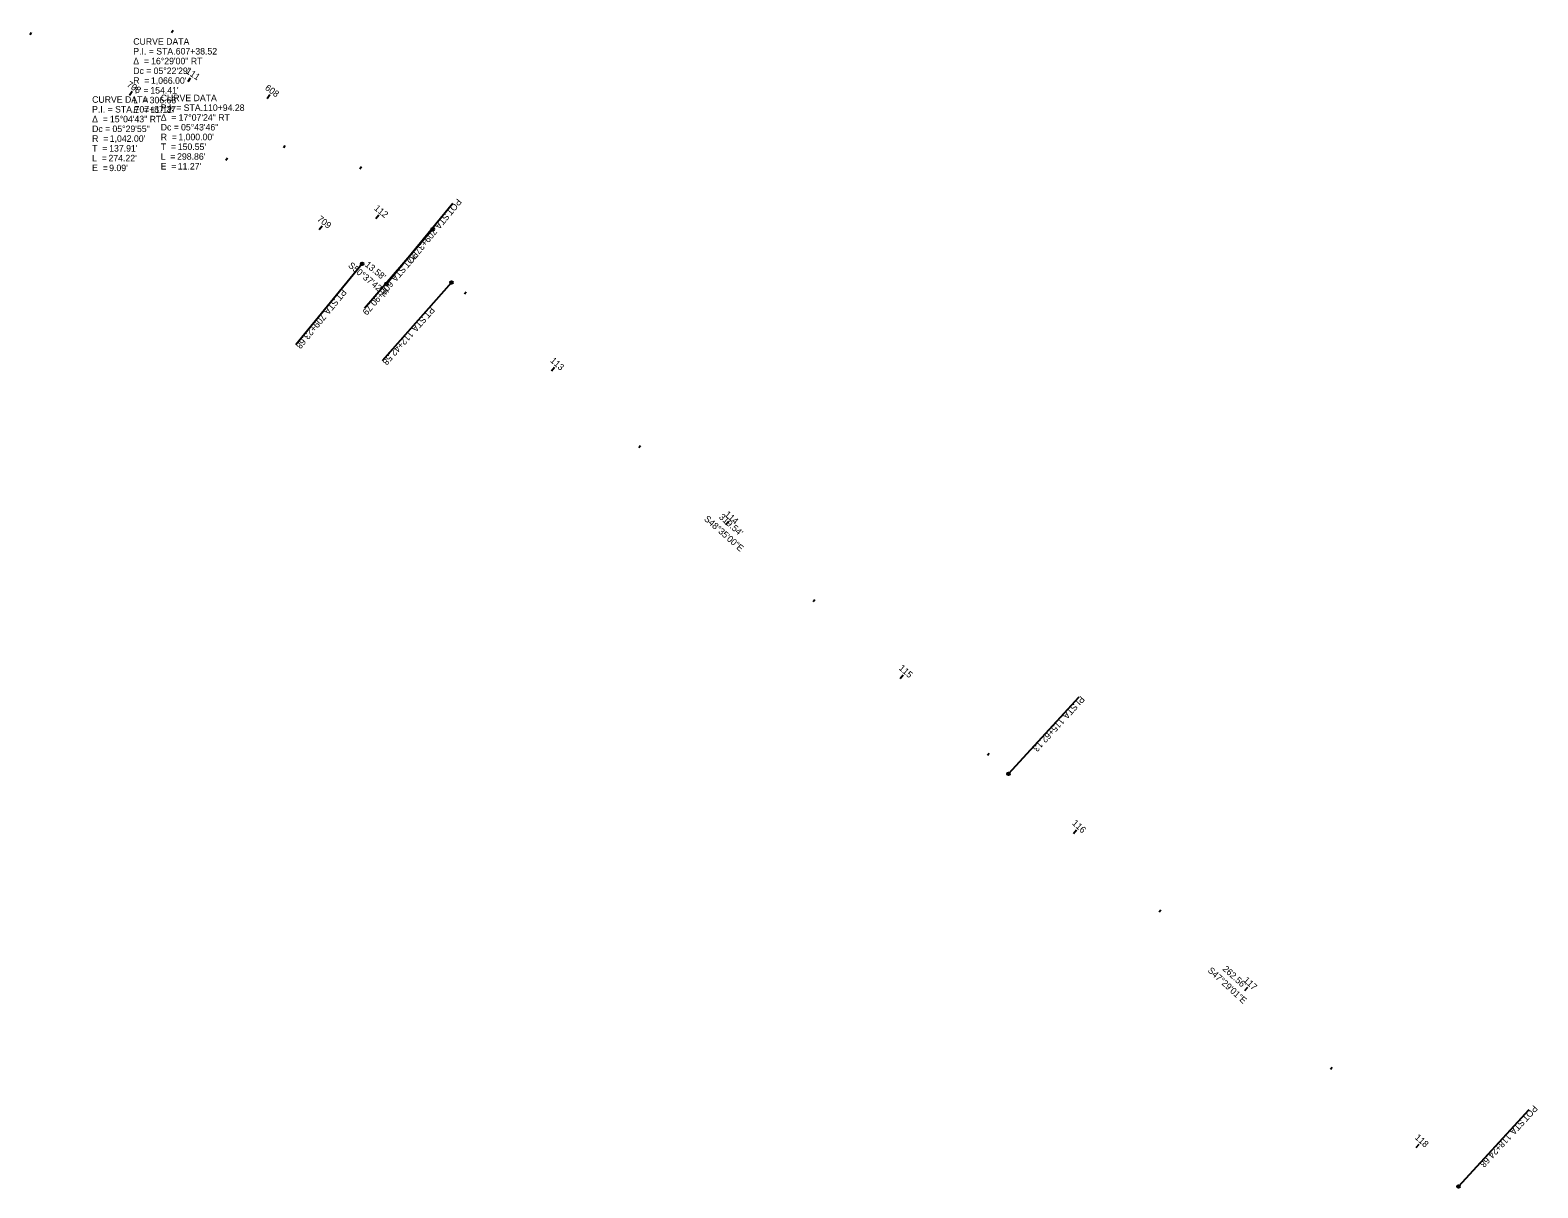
# Model space of a CAD drawing. Extents: x 1600023 to 1602131, y 285824 to 287284.
# Drawn here: x 1601483 to 1602131, y 285824 to 286322 of the extents above; entities that cross this region are included whole.
import ezdxf

# ---------------------------------------------------------------- set-up
doc = ezdxf.new("R2010")
doc.units = 0
for name, color, linetype in [('_CIVIL_CONSTRUCTION', 7, 'Continuous'), ('Default', 7, 'Continuous'), ('GE_P_Alignment', 7, 'Continuous'), ('PF_P_Grade_Line', 7, 'Continuous'), ('PF_X_Ground_Line', 7, 'Continuous'), ('SC_Scratch6', 7, 'Continuous')]:
    doc.layers.add(name, color=color, linetype=linetype)

msp = doc.modelspace()

# ---------------------------------------------------------------- linework, layer by layer
at = {"layer": '_CIVIL_CONSTRUCTION'}
for p, q in [((1601664.01, 286213.55), (1601634.24, 286179.8)), ((1601903.64, 286002.16), (1601934.05, 286035.33)), ((1602097.17, 285824.72), (1602127.58, 285857.89))]:
    msp.add_line(p, q, dxfattribs=at)
for centre in [(1601664.01, 286213.55), (1601903.64, 286002.16), (1602097.17, 285824.72)]:
    msp.add_circle(centre, 0.6, dxfattribs=at)
at = {"layer": 'Default'}
for p, q in [((1601543.6, 286321.05), (1601544.25, 286322.06)), ((1601482.78, 286320.01), (1601483.38, 286321.05)), ((1601525.55, 286294.12), (1601526.63, 286295.8)), ((1601584.77, 286292.7), (1601585.95, 286294.32)), ((1601567.03, 286266.2), (1601567.72, 286267.18)), ((1601624.57, 286262.44), (1601625.32, 286263.38)), ((1601636.09, 286212.89), (1601664.64, 286247.68)), ((1601607.11, 286236.32), (1601608.35, 286237.9)), ((1601655.97, 286236.4), (1601626.58, 286202.32)), ((1601625.59, 286221.51), (1601597.05, 286186.72))]:
    msp.add_line(p, q, dxfattribs=at)
for centre in [(1601655.97, 286236.4), (1601625.59, 286221.51), (1601636.09, 286212.89)]:
    msp.add_circle(centre, 0.6, dxfattribs=at)
at = {"layer": 'SC_Scratch6'}
for p, q in [((1601550.73, 286299.94), (1601551.83, 286301.61)), ((1601591.84, 286271.5), (1601592.55, 286272.46)), ((1601631.48, 286241.03), (1601632.74, 286242.58)), ((1601669.57, 286208.64), (1601670.36, 286209.54)), ((1601707.07, 286175.57), (1601708.39, 286177.06)), ((1601744.56, 286142.49), (1601745.36, 286143.39)), ((1601782.06, 286109.41), (1601783.38, 286110.91)), ((1601819.55, 286076.34), (1601820.35, 286077.24)), ((1601857.05, 286043.26), (1601858.37, 286044.76)), ((1601894.55, 286010.18), (1601895.34, 286011.08)), ((1601931.56, 285976.57), (1601932.91, 285978.04)), ((1601968.41, 285942.78), (1601969.22, 285943.66)), ((1602005.26, 285908.99), (1602006.62, 285910.46)), ((1602042.12, 285875.2), (1602042.93, 285876.08)), ((1602078.97, 285841.41), (1602080.32, 285842.88))]:
    msp.add_line(p, q, dxfattribs=at)

# ---------------------------------------------------------------- texts
at = {"layer": '_CIVIL_CONSTRUCTION'}
for s, rotation, p in [(' STA. ', 228.58344, (1601652.12, 286200.01)), ('PT', 228.58344, (1601655.04, 286203.32)), ('112+42.58', 228.58344, (1601645.87, 286192.92)), (' STA. ', 227.48364, (1601932.34, 286033.41)), ('PI', 227.48364, (1601934.64, 286035.91)), ('115+62.13', 227.48364, (1601925.96, 286026.44)), ('POT', 227.48364, (1602129.49, 285859.92)), (' STA. ', 227.48364, (1602124.63, 285854.61)), ('118+24.68', 227.48364, (1602118.24, 285847.64))]:
    msp.add_text(s, height=2.8, rotation=rotation, dxfattribs=at).set_placement(p)
at = {"layer": 'Default'}
for s, p in [('CURVE DATA', (1601527.14, 286315.78)), ('Δ  = ', (1601527.14, 286307.38)), ('P.I. = STA. ', (1601527.14, 286311.58)), ('16°29\'00" RT', (1601534.82, 286307.38)), ('607+38.52', (1601545.41, 286311.58)), ('Dc = ', (1601527.14, 286303.18)), ('05°22\'29"', (1601535.88, 286303.18)), ('T  = ', (1601527.14, 286294.78)), ('R  = ', (1601527.14, 286298.98)), ("154.41'", (1601534.48, 286294.78)), ("1,066.00'", (1601534.72, 286298.98)), ('CURVE DATA', (1601509.44, 286290.82)), ('P.I. = STA. ', (1601509.44, 286286.62)), ('L  = ', (1601527.14, 286290.58)), ('E  = ', (1601527.14, 286286.38)), ('707+87.37', (1601527.7, 286286.62)), ("306.68'", (1601534.18, 286290.58)), ("11.12'", (1601534.48, 286286.38)), ('Δ  = ', (1601509.44, 286282.42)), ('15°04\'43" RT', (1601517.11, 286282.42)), ('Dc = ', (1601509.44, 286278.22)), ('R  = ', (1601509.44, 286274.02)), ("1,042.00'", (1601517.02, 286274.02)), ('05°29\'55"', (1601518.18, 286278.22)), ('T  = ', (1601509.44, 286269.82)), ("137.91'", (1601516.78, 286269.82)), ('L  = ', (1601509.44, 286265.62)), ('E  = ', (1601509.44, 286261.42)), ("274.22'", (1601516.48, 286265.62)), ("9.09'", (1601516.78, 286261.42))]:
    msp.add_text(s, height=2.8, dxfattribs=at).set_placement(p)
for s, rotation, p in [('708', 327.42926, (1601524.09, 286298.02)), ('608', 324.10344, (1601583.54, 286296.68)), ('POT', 230.62832, (1601666.49, 286249.87)), ('709', 321.93062, (1601606.04, 286240.34)), (' STA. ', 230.62832, (1601661.92, 286244.3)), ('709+37.27', 230.62832, (1601655.93, 286237)), ('POT', 229.22344, (1601648.01, 286227.11)), ('S50°37\'42"E', 320.62832, (1601619.34, 286220.43)), ("13.58'", 320.62832, (1601626.57, 286220.76)), (' STA. ', 229.22344, (1601643.31, 286221.65)), ('608+90.79', 229.22344, (1601637.14, 286214.5)), (' STA. ', 230.62832, (1601614.19, 286207.55)), ('PT', 230.62832, (1601616.99, 286210.96)), ('709+23.68', 230.62832, (1601608.2, 286200.25))]:
    msp.add_text(s, height=2.8, rotation=rotation, dxfattribs=at).set_placement(p)
at = {"layer": 'GE_P_Alignment'}
for s, rotation, p in [('S48°35\'00"E', 318.58344, (1601772.45, 286111.49)), ('S47°29\'01"E', 317.48364, (1601989.1, 285917.3))]:
    msp.add_text(s, height=2.8, rotation=rotation, dxfattribs=at).set_placement(p)
at = {"layer": 'PF_P_Grade_Line'}
for s, rotation, p in [("319.54'", 318.58344, (1601778.84, 286112.3)), ("262.56'", 317.48364, (1601995.51, 285917.99))]:
    msp.add_text(s, height=2.8, rotation=rotation, dxfattribs=at).set_placement(p)
at = {"layer": 'PF_X_Ground_Line'}
for s, p in [('CURVE DATA', (1601538.95, 286291.51)), ('P.I. = STA. ', (1601538.95, 286287.31)), ('110+94.28', (1601557.21, 286287.31)), ('Δ  = ', (1601538.95, 286283.11)), ('17°07\'24" RT', (1601546.62, 286283.11)), ('Dc = ', (1601538.95, 286278.91)), ('R  = ', (1601538.95, 286274.71)), ("1,000.00'", (1601546.53, 286274.71)), ('05°43\'46"', (1601547.69, 286278.91)), ('T  = ', (1601538.95, 286270.51)), ("150.55'", (1601546.28, 286270.51)), ('L  = ', (1601538.95, 286266.31)), ('E  = ', (1601538.95, 286262.11)), ("298.86'", (1601545.99, 286266.31)), ("11.27'", (1601546.29, 286262.11))]:
    msp.add_text(s, height=2.8, dxfattribs=at).set_placement(p)
at = {"layer": 'SC_Scratch6'}
for s, rotation, p in [('111', 326.75286, (1601549.47, 286303.76)), ('112', 321.02328, (1601630.51, 286245.04)), ('113', 318.58344, (1601706.27, 286179.6)), ('114', 318.58344, (1601781.26, 286113.45)), ('115', 318.58344, (1601856.23, 286047.32)), ('116', 317.48364, (1601930.77, 285980.68)), ('117', 317.48364, (1602004.44, 285913.14)), ('118', 317.48364, (1602078.2, 285845.5))]:
    msp.add_text(s, height=2.8, rotation=rotation, dxfattribs=at).set_placement(p)

doc.saveas('drawing.dxf')
